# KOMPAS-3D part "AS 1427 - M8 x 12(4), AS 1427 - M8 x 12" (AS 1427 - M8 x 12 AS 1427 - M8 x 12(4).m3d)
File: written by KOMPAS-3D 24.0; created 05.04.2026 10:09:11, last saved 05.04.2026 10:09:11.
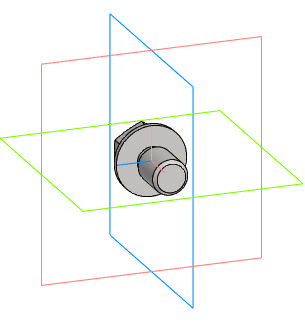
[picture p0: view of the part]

Document properties: Автор: R2D2; Полное имя файла: E:\Работа\Зайцев\Аксессуары для пневмоприводов\Ручной дублер DN.ru\MON3-700-T38-ISO Ручной дублер DN.ru\исходные материалы\AS 1427 - M8 x 12 AS 1427 - M8 x 12(4).m3d

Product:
- Body: Solid1  | qty 1
- Part/product: AS 1427 - M8 x 12(4)  | designation AS 1427 - M8 x 12
    Комментарий: Винты мелкие крепежные   метрические ISO
    additional columns: Сталь, мягкая

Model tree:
1. Solid1  (labels: Solid1)

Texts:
  AS 1427 - M8 x 12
